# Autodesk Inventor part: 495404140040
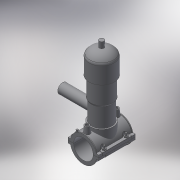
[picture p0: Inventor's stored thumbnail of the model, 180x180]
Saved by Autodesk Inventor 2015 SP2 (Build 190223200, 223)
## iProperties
Created: 2017-07
Part Number: 495404140040
Material: Generic
Description: PLASSON TAPPING VALVE 140-40
Document SubType Name: Modeling
Designer: KIM
Density: 1 g/cm^3
Appearance: Default
Author: KIM
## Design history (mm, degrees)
derived "495404-4954S4.ipt"
feature "Solid1::495404-4954S4.ipt"
feature "Solid2::495404-4954S4.ipt"
tag "TaggingFeature1"
body "Solid1"
body "Solid2"
other parameters: "d3" = 35, "d4" = 118, "d5" = 0, "d6" = 0.1, "d8" = 0, "d19" = 6, "d20" = 6, "d21" = 70.8, "d23" = 0, "d24" = 35.4, "d26" = 0, "d27" = 3, "d28" = 3, "d29" = 3, "d30" = 46.66667, "d31" = 6, "d32" = 0, "d33" = 0, "d34" = 0.6, "d40" = 87.36, "d70" = 15, "d72" = 0, "d73" = 6, "d75" = 5, "d76" = 0, "d77" = 7, "d79" = 15, "d80" = 47.2, "d82" = 5 deg, "d84" = 4, "d85" = 14, "d86" = 0, "d87" = 3, "d88" = 0, "d89" = 1, "d90" = 1, "d91" = 94.4, "d92" = 0, "d93" = 0.5, "d94" = 73.68421, "d96" = 173.04, "d97" = 2.36, "d98" = 0, "d120" = 140 deg, "d121" = 24.228, "d122" = 20 deg, "d123" = 336, "d124" = 100.8, "d126" = 0, "d143" = 144.2, "d145" = 21.53846, "d149" = 2.1, "d150" = 23.69231, "d153" = 118, "d154" = 0, "d156" = 84, "d157" = 160 deg, "d159" = 5.6, "d161" = 2.1, "d162" = 70.8, "d163" = 0, "d167" = 14, "d168" = 81.95122, "d170" = 3, "d172" = 0, "d173" = 1, "d176" = 20 deg, "d177" = 9.8, "d178" = 28, "d180" = 0, "d183" = 11.2, "d184" = 7.84, "d185" = 38.35, "d186" = 38.35, "d187" = 84, "d188" = 8.4, "d189" = 9.8, "d190" = 0, "d191" = 126, "d193" = 6.8, "d194" = 2.95, "d195" = 90 deg, "d197" = 0, "d199" = 0, "d205" = 14.64, "d206" = 81.33333, "d207" = 244, "d208" = 224.48, "d209" = 207.4, "d210" = 200.08, "d211" = 146.4, "d212" = 85.4, "d213" = 65.88, "d214" = 73.2, "d216" = 19.52, "d217" = 70.76, "d218" = 80.52, "d222" = 0, "d223" = 168, "d224" = 137, "d225" = 46, "d229" = 137, "d230" = 0, "H_" = 137, "L_" = 118, "d_t" = 6, "H_1" = 46, "H_2" = 244, "d148" = 2.1, "d160" = 2.1, "d169" = 3, "d192" = 6.8, "d228" = 32
